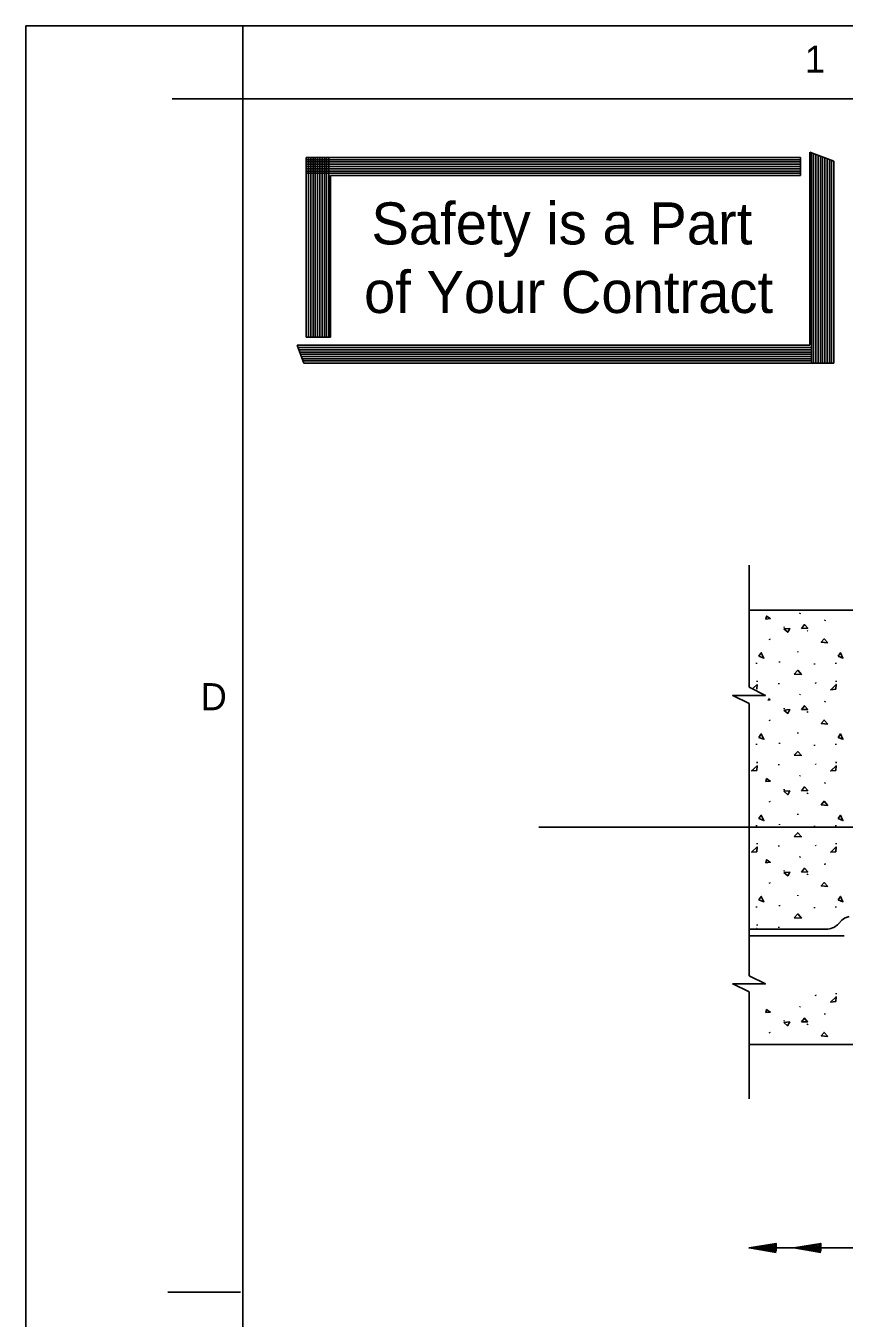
# Model space of a CAD drawing. Extents: x 22369.6 to 22384.3, y 22369.6 to 22381.8.
# Drawn here: x 22369.621 to 22371.507, y 22377.981 to 22380.957 of the extents above; entities that cross this region are included whole.
import ezdxf

# ---------------------------------------------------------------- set-up
doc = ezdxf.new("R2010")
doc.units = 0
for name, color, linetype in [('Level 1', 7, 'Continuous'), ('Level 10', 7, 'Continuous'), ('Level 8', 7, 'Continuous'), ('Level 9', 7, 'Continuous')]:
    doc.layers.add(name, color=color, linetype=linetype)

msp = doc.modelspace()

# ---------------------------------------------------------------- linework, layer by layer
at = {"layer": 'Level 1'}
for p, q in [((22371.2877, 22379.4344), (22371.2877, 22379.7155)), ((22371.2877, 22378.7699), (22371.2877, 22379.397)), ((22370.8029, 22379.1117), (22371.5521, 22379.1117)), ((22371.3999, 22378.9536), (22371.3997, 22378.9556)), ((22371.305, 22378.9272), (22371.305, 22378.9297)), ((22371.3575, 22378.9302), (22371.3579, 22378.9321)), ((22371.4387, 22378.9252), (22371.438, 22378.9277)), ((22371.4872, 22378.9272), (22371.4872, 22378.9297)), ((22371.3059, 22378.8858), (22371.3059, 22378.8881)), ((22371.356, 22378.8804), (22371.356, 22378.8829)), ((22371.4936, 22378.8896), (22371.5012, 22378.8978)), ((22371.2877, 22378.8775), (22371.4694, 22378.8775)), ((22371.2877, 22378.8619), (22371.5067, 22378.8619)), ((22371.2877, 22378.4867), (22371.2877, 22378.7326)), ((22371.2877, 22378.1431), (22371.2877, 22378.1431)), ((22371.2877, 22378.1431), (22372.3014, 22378.1431)), ((22371.305, 22378.1431), (22371.305, 22378.1431)), ((22371.3904, 22378.1431), (22371.3904, 22378.1431)), ((22371.4077, 22378.1431), (22371.4077, 22378.1431))]:
    msp.add_line(p, q, dxfattribs=at)
for points in [[(22369.6213, 22380.9573), (22384.2881, 22380.9573), (22384.2881, 22369.6213), (22369.6213, 22369.6213)], [(22371.3104, 22378.9447), (22371.3218, 22378.9403), (22371.3158, 22378.9526)], [(22371.4926, 22378.9447), (22371.504, 22378.9403), (22371.498, 22378.9526)], [(22371.3917, 22378.9035), (22371.3997, 22378.9121), (22371.4082, 22378.9026)]]:
    msp.add_lwpolyline(points, close=True, dxfattribs=at)
for points in [[(22371.2877, 22379.397), (22371.2502, 22379.4156), (22371.3251, 22379.4156), (22371.2877, 22379.4344)], [(22371.3059, 22378.8795), (22371.3045, 22378.8782)], [(22371.3058, 22378.8782), (22371.3059, 22378.8795)], [(22371.2877, 22378.7326), (22371.2502, 22378.7512), (22371.3251, 22378.7512), (22371.2877, 22378.7699)], [(22371.35, 22378.1328), (22371.2877, 22378.1431), (22371.35, 22378.1535), (22371.35, 22378.1358), (22371.305, 22378.1431), (22371.3474, 22378.1501), (22371.3474, 22378.1388), (22371.3217, 22378.1431), (22371.3447, 22378.1468), (22371.3447, 22378.1421), (22371.339, 22378.1431)], [(22371.4527, 22378.1328), (22371.3904, 22378.1431), (22371.4527, 22378.1535), (22371.4527, 22378.1358), (22371.4077, 22378.1431), (22371.4501, 22378.1501), (22371.4501, 22378.1388), (22371.4244, 22378.1431), (22371.4474, 22378.1468), (22371.4474, 22378.1421), (22371.4417, 22378.1431)]]:
    msp.add_lwpolyline(points, dxfattribs=at)
for centre, radius, start, end in [((22371.4655, 22378.9157), 0.0384, 275.7693, 317.1676), ((22371.5292, 22378.8642), 0.0437, 104.9327, 129.732)]:
    msp.add_arc(centre, radius, start, end, dxfattribs=at)
at = {"layer": 'Level 10'}
for p, q in [((22370.1213, 22380.7893), (22370.1213, 22380.9573)), ((22369.9585, 22380.7893), (22370.1196, 22380.7893)), ((22371.4274, 22380.6666), (22371.4274, 22380.2219)), ((22371.4274, 22380.6666), (22371.4831, 22380.6459)), ((22371.4311, 22380.6652), (22371.4311, 22380.1802)), ((22370.2674, 22380.6542), (22371.4064, 22380.6542)), ((22370.2674, 22380.6542), (22370.2674, 22380.2406)), ((22370.2674, 22380.6489), (22371.4064, 22380.6489)), ((22370.2674, 22380.6439), (22371.4064, 22380.6439)), ((22370.2674, 22380.6386), (22371.4064, 22380.6386)), ((22370.2728, 22380.6542), (22370.2728, 22380.2406)), ((22370.2778, 22380.6542), (22370.2778, 22380.2406)), ((22370.2831, 22380.6542), (22370.2831, 22380.2406)), ((22370.2881, 22380.6542), (22370.2881, 22380.2406)), ((22370.2934, 22380.6542), (22370.2934, 22380.2406)), ((22370.2988, 22380.6542), (22370.2988, 22380.2406)), ((22370.3038, 22380.6542), (22370.3038, 22380.2406)), ((22370.3091, 22380.6542), (22370.3091, 22380.2406)), ((22370.3144, 22380.6542), (22370.3144, 22380.2406)), ((22370.3194, 22380.6542), (22370.3194, 22380.2406)), ((22371.4064, 22380.6542), (22371.4064, 22380.6126)), ((22371.4361, 22380.6632), (22371.4361, 22380.1802)), ((22371.4414, 22380.6612), (22371.4414, 22380.1802)), ((22371.4468, 22380.6592), (22371.4468, 22380.1802)), ((22371.4518, 22380.6576), (22371.4518, 22380.1802)), ((22371.4571, 22380.6556), (22371.4571, 22380.1802)), ((22371.4621, 22380.6536), (22371.4621, 22380.1802)), ((22371.4674, 22380.6516), (22371.4674, 22380.1802)), ((22371.4728, 22380.6499), (22371.4728, 22380.1802)), ((22371.4778, 22380.6459), (22371.4778, 22380.1802)), ((22371.4831, 22380.6459), (22371.4831, 22380.1802)), ((22370.2674, 22380.6332), (22371.4064, 22380.6332)), ((22370.2674, 22380.6282), (22371.4064, 22380.6282)), ((22370.2674, 22380.6229), (22371.4064, 22380.6229)), ((22370.2674, 22380.6179), (22371.4064, 22380.6179)), ((22370.3231, 22380.6126), (22371.4064, 22380.6126)), ((22370.3231, 22380.6126), (22370.3231, 22380.2406)), ((22370.2464, 22380.2219), (22371.4274, 22380.2219)), ((22370.2464, 22380.2219), (22370.2618, 22380.1802)), ((22370.2674, 22380.2406), (22370.3231, 22380.2406)), ((22370.2484, 22380.2166), (22371.4311, 22380.2166)), ((22370.2501, 22380.2116), (22371.4311, 22380.2116)), ((22370.2521, 22380.2062), (22371.4311, 22380.2062)), ((22370.2541, 22380.2009), (22371.4311, 22380.2009)), ((22370.2561, 22380.1959), (22371.4311, 22380.1959)), ((22370.2581, 22380.1906), (22371.4311, 22380.1906)), ((22370.2598, 22380.1856), (22371.4311, 22380.1856)), ((22370.2618, 22380.1802), (22371.4831, 22380.1802)), ((22372.2493, 22379.6114), (22371.2877, 22379.6114)), ((22372.2493, 22378.6119), (22371.2877, 22378.6119)), ((22369.9481, 22378.0413), (22370.1161, 22378.0413))]:
    msp.add_line(p, q, dxfattribs=at)
at = {"layer": 'Level 8'}
for p, q in [((22371.4044, 22379.6036), (22371.4053, 22379.6055)), ((22371.3684, 22379.5716), (22371.3685, 22379.5734)), ((22371.4216, 22379.5632), (22371.4228, 22379.5653)), ((22371.4622, 22379.5868), (22371.4626, 22379.5892)), ((22371.3357, 22379.5437), (22371.3346, 22379.5459)), ((22371.3999, 22379.5147), (22371.3997, 22379.5167)), ((22371.305, 22379.4883), (22371.305, 22379.4908)), ((22371.3575, 22379.4913), (22371.3579, 22379.4932)), ((22371.4387, 22379.4863), (22371.438, 22379.4888)), ((22371.4872, 22379.4883), (22371.4872, 22379.4908)), ((22371.3059, 22379.4469), (22371.3059, 22379.4492)), ((22371.356, 22379.4415), (22371.356, 22379.444)), ((22371.4412, 22379.4432), (22371.4405, 22379.445)), ((22371.4881, 22379.4469), (22371.4881, 22379.4492)), ((22371.4044, 22379.4165), (22371.4053, 22379.4185)), ((22371.3684, 22379.3845), (22371.3685, 22379.3863)), ((22371.4622, 22379.3997), (22371.4626, 22379.4021)), ((22371.3357, 22379.3567), (22371.3346, 22379.3589)), ((22371.4216, 22379.3762), (22371.4228, 22379.3783)), ((22371.3999, 22379.3276), (22371.3997, 22379.3297)), ((22371.305, 22379.3013), (22371.305, 22379.3038)), ((22371.3575, 22379.3043), (22371.3579, 22379.3061)), ((22371.4387, 22379.2993), (22371.438, 22379.3018)), ((22371.4872, 22379.3013), (22371.4872, 22379.3038)), ((22371.3059, 22379.2598), (22371.3059, 22379.2622)), ((22371.356, 22379.2545), (22371.356, 22379.257)), ((22371.4412, 22379.2562), (22371.4405, 22379.258)), ((22371.4881, 22379.2598), (22371.4881, 22379.2622)), ((22371.4044, 22379.2295), (22371.4053, 22379.2314)), ((22371.4622, 22379.2127), (22371.4626, 22379.2151)), ((22371.3684, 22379.1975), (22371.3685, 22379.1993)), ((22371.4216, 22379.1891), (22371.4228, 22379.1912)), ((22371.3357, 22379.1696), (22371.3346, 22379.1718)), ((22371.305, 22379.1143), (22371.305, 22379.1168)), ((22371.3575, 22379.1172), (22371.3579, 22379.1191)), ((22371.3999, 22379.1406), (22371.3997, 22379.1426)), ((22371.4872, 22379.1143), (22371.4872, 22379.1168)), ((22371.4387, 22379.1123), (22371.438, 22379.1148)), ((22371.3059, 22379.0728), (22371.3059, 22379.0751)), ((22371.356, 22379.0674), (22371.356, 22379.0699)), ((22371.4412, 22379.0691), (22371.4405, 22379.0709)), ((22371.4881, 22379.0728), (22371.4881, 22379.0751)), ((22371.4044, 22379.0424), (22371.4053, 22379.0444)), ((22371.4622, 22379.0256), (22371.4626, 22379.0281)), ((22371.3684, 22379.0104), (22371.3685, 22379.0123)), ((22371.4216, 22379.0021), (22371.4228, 22379.0042)), ((22371.3357, 22378.9826), (22371.3346, 22378.9848)), ((22371.488, 22378.7277), (22371.488, 22378.73)), ((22371.4411, 22378.724), (22371.4404, 22378.7258)), ((22371.4043, 22378.6973), (22371.4052, 22378.6993)), ((22371.4621, 22378.6805), (22371.4625, 22378.6829)), ((22371.3683, 22378.6653), (22371.3684, 22378.6671)), ((22371.4215, 22378.657), (22371.4227, 22378.6591)), ((22371.3356, 22378.6375), (22371.3345, 22378.6397))]:
    msp.add_line(p, q, dxfattribs=at)
for points in [[(22371.3264, 22379.5911), (22371.3365, 22379.5924), (22371.328, 22379.5981)], [(22371.3677, 22379.5688), (22371.3766, 22379.5609), (22371.3814, 22379.5698)], [(22371.4085, 22379.5698), (22371.4152, 22379.5787), (22371.4227, 22379.5701)], [(22371.4688, 22379.5362), (22371.4606, 22379.5457), (22371.454, 22379.5378)], [(22371.3104, 22379.5058), (22371.3218, 22379.5014), (22371.3158, 22379.5137)], [(22371.4926, 22379.5058), (22371.504, 22379.5014), (22371.498, 22379.5137)], [(22371.3917, 22379.4646), (22371.3997, 22379.4732), (22371.4082, 22379.4637)], [(22371.4875, 22379.4295), (22371.4881, 22379.4406), (22371.4757, 22379.4286)], [(22371.4085, 22379.3828), (22371.4152, 22379.3916), (22371.4227, 22379.3831)], [(22371.3677, 22379.3818), (22371.3766, 22379.3739), (22371.3814, 22379.3828)], [(22371.4688, 22379.3492), (22371.4606, 22379.3587), (22371.454, 22379.3508)], [(22371.3104, 22379.3188), (22371.3218, 22379.3144), (22371.3158, 22379.3267)], [(22371.4926, 22379.3188), (22371.504, 22379.3144), (22371.498, 22379.3267)], [(22371.3917, 22379.2776), (22371.3997, 22379.2862), (22371.4082, 22379.2767)], [(22371.3052, 22379.2425), (22371.3059, 22379.2536), (22371.2935, 22379.2416)], [(22371.4875, 22379.2425), (22371.4881, 22379.2536), (22371.4757, 22379.2416)], [(22371.3264, 22379.2171), (22371.3365, 22379.2183), (22371.328, 22379.2241)], [(22371.3677, 22379.1948), (22371.3766, 22379.1868), (22371.3814, 22379.1957)], [(22371.4085, 22379.1957), (22371.4152, 22379.2046), (22371.4227, 22379.1961)], [(22371.4688, 22379.1621), (22371.4606, 22379.1716), (22371.454, 22379.1638)], [(22371.3104, 22379.1318), (22371.3218, 22379.1273), (22371.3158, 22379.1396)], [(22371.4926, 22379.1318), (22371.504, 22379.1273), (22371.498, 22379.1396)], [(22371.3917, 22379.0906), (22371.3997, 22379.0991), (22371.4082, 22379.0896)], [(22371.3052, 22379.0554), (22371.3059, 22379.0666), (22371.2935, 22379.0545)], [(22371.4875, 22379.0554), (22371.4881, 22379.0666), (22371.4757, 22379.0545)], [(22371.3264, 22379.03), (22371.3365, 22379.0313), (22371.328, 22379.037)], [(22371.3677, 22379.0077), (22371.3766, 22378.9998), (22371.3814, 22379.0087)], [(22371.4085, 22379.0087), (22371.4152, 22379.0176), (22371.4227, 22379.009)], [(22371.4688, 22378.9751), (22371.4606, 22378.9846), (22371.454, 22378.9767)], [(22371.4873, 22378.7103), (22371.488, 22378.7214), (22371.4756, 22378.7094)], [(22371.3263, 22378.6849), (22371.3364, 22378.6862), (22371.3279, 22378.6919)], [(22371.4084, 22378.6636), (22371.4151, 22378.6724), (22371.4226, 22378.6639)], [(22371.3676, 22378.6626), (22371.3765, 22378.6547), (22371.3813, 22378.6636)], [(22371.4687, 22378.63), (22371.4605, 22378.6395), (22371.4538, 22378.6316)]]:
    msp.add_lwpolyline(points, close=True, dxfattribs=at)
for points in [[(22371.3059, 22379.4406), (22371.297, 22379.432)], [(22371.3053, 22379.4299), (22371.3059, 22379.4406)], [(22371.3307, 22379.4046), (22371.3365, 22379.4054)], [(22371.3365, 22379.4054), (22371.3326, 22379.408)]]:
    msp.add_lwpolyline(points, dxfattribs=at)
at = {"layer": 'Level 9'}
for p, q in [((22370.1213, 22369.7893), (22370.1213, 22380.7893)), ((22370.1213, 22380.7893), (22383.2041, 22380.7893))]:
    msp.add_line(p, q, dxfattribs=at)

# ---------------------------------------------------------------- texts
at = {"layer": 'Level 1'}
for s, p in [('1', (22371.4161, 22380.8493)), ('D', (22370.0241, 22379.3813))]:
    msp.add_text(s, height=0.0624, dxfattribs=at).set_placement(p)
at = {"layer": 'Level 10'}
for s, p in [('Safety is a Part', (22370.4175, 22380.454)), ('of Your Contract', (22370.4005, 22380.296))]:
    msp.add_text(s, height=0.096792, dxfattribs=at).set_placement(p)

doc.saveas('drawing.dxf')
